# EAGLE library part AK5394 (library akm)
Audio ADC Super High Performance, 192kHz, 24-Bit, 2ch, Delta Sigma
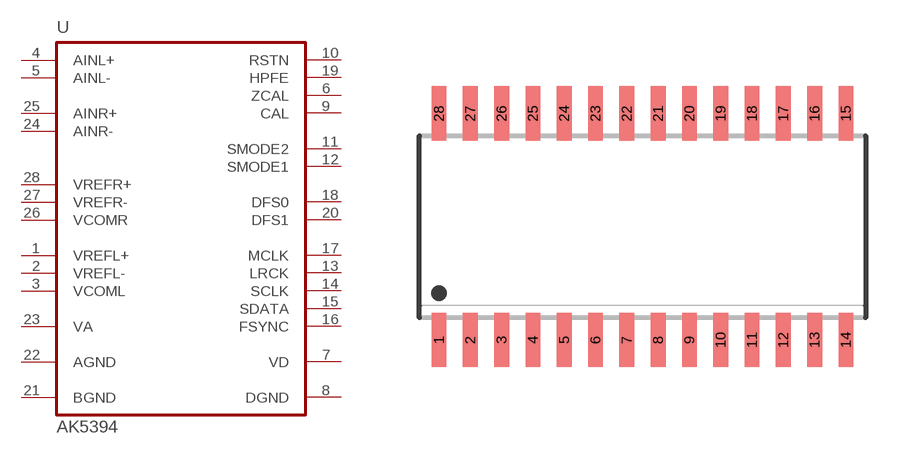
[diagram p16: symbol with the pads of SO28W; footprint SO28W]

Designator prefix U

## AK5394  [SO28W]
1  VREFL+  out
2  VREFL-  out
3  VCOML  out
4  AINL+  in
5  AINL-  in
6  ZCAL  in
7  VD  pwr
8  DGND  pwr
9  CAL  out
10  RSTN  in
11  SMODE2  in
12  SMODE1  in
13  LRCK
14  SCLK
15  SDATA  out
16  FSYNC
17  MCLK  in
18  DFS0  in
19  HPFE  in
20  DFS1  in
21  BGND  pwr
22  AGND  pwr
23  VA  pwr
24  AINR-  in
25  AINR+  in
26  VCOMR  out
27  VREFR-  out
28  VREFR+  out

## Footprint SO28W (pad centres in mm)
SMALL OUTLINE INTEGRATED CIRCUIT wide body 7.5 mm/JEDEC MO-119AB
smd 0.6 x 2.2: 1 -8.255,-4.6; 2 -6.985,-4.6; 3 -5.715,-4.6; 4 -4.445,-4.6; 5 -3.175,-4.6; 6 -1.905,-4.6; 7 -0.635,-4.6; 8 0.635,-4.6; 9 1.905,-4.6; 10 3.175,-4.6; 11 4.445,-4.6; 12 5.715,-4.6; 13 6.985,-4.6; 14 8.255,-4.6; 15 8.255,4.6; 16 6.985,4.6; 17 5.715,4.6; 18 4.445,4.6; 19 3.175,4.6; 20 1.905,4.6; 21 0.635,4.6; 22 -0.635,4.6; 23 -1.905,4.6; 24 -3.175,4.6; 25 -4.445,4.6; 26 -5.715,4.6; 27 -6.985,4.6; 28 -8.255,4.6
